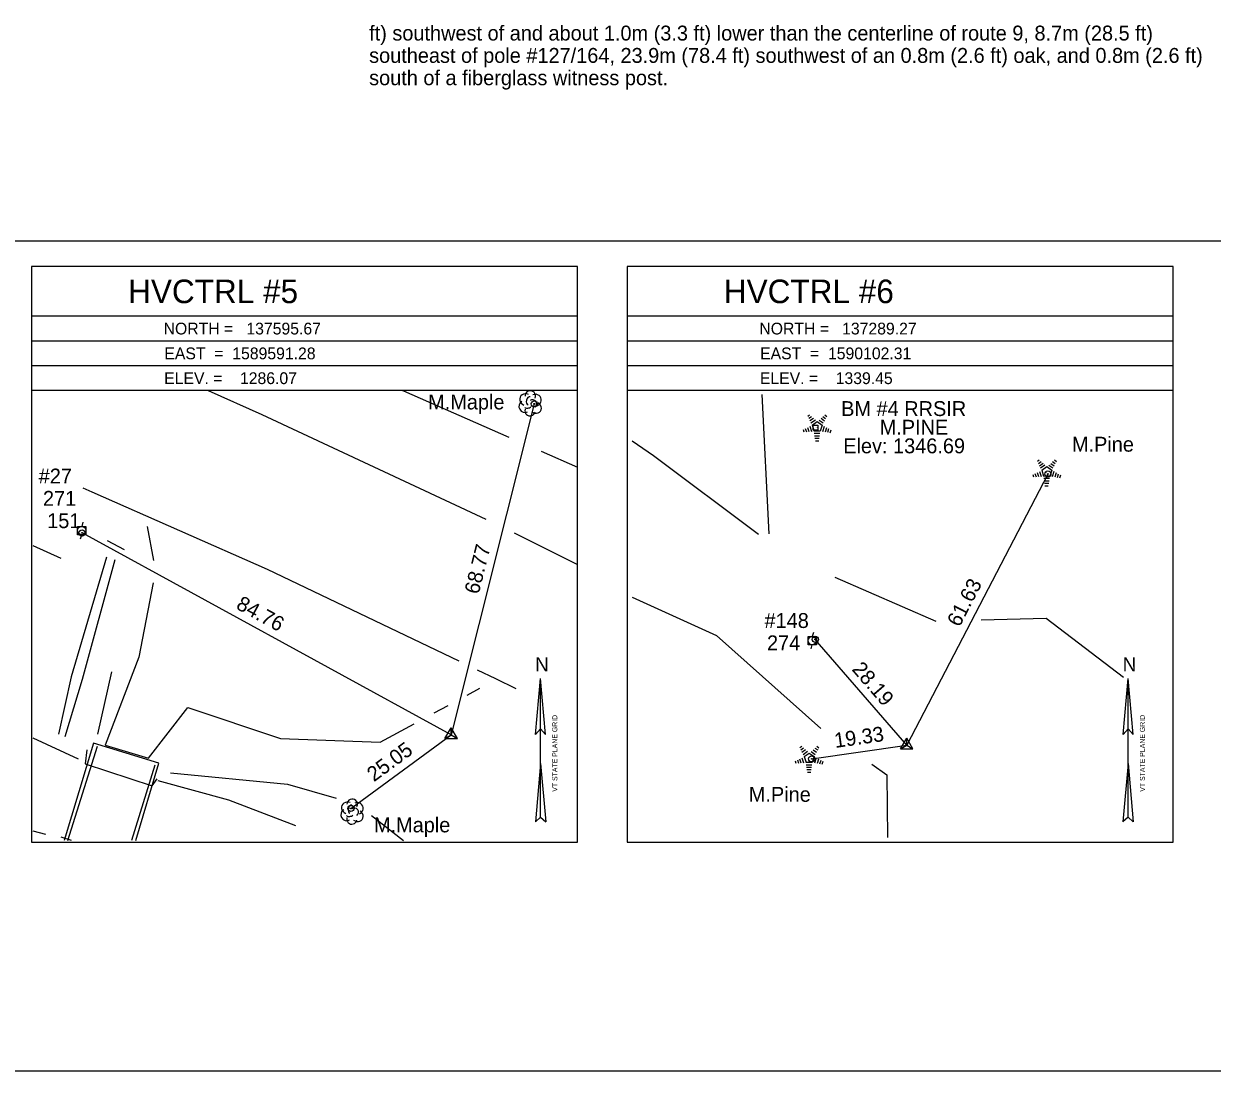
# Model space of a CAD drawing. Extents: x 1589528 to 1590208, y 135765 to 136632.
# Drawn here: x 1589811.7 to 1590051.1, y 136211.9 to 136423 of the extents above; entities that cross this region are included whole.
import ezdxf

# ---------------------------------------------------------------- set-up
doc = ezdxf.new("R2010")
doc.units = 0
for name, color, linetype in [('BELB', 7, 'Continuous'), ('BR', 7, 'Continuous'), ('BSUBM', 7, 'Continuous'), ('C_C', 7, 'Continuous'), ('CBP', 7, 'Continuous'), ('CPBM', 7, 'Continuous'), ('CPSM', 7, 'Continuous'), ('DD', 7, 'Continuous'), ('Default', 7, 'Continuous'), ('DHW', 7, 'Continuous'), ('L_C', 7, 'Continuous'), ('LAWA', 7, 'Continuous'), ('LAWE', 7, 'Continuous'), ('Level 1', 7, 'Continuous'), ('Level 2', 7, 'Continuous'), ('LTC', 7, 'Continuous'), ('LTD', 7, 'Continuous'), ('LWS', 7, 'Continuous'), ('NBL1', 7, 'Continuous'), ('PET', 7, 'Continuous'), ('RDG', 7, 'Continuous'), ('U_C', 7, 'Continuous'), ('UP', 7, 'Continuous')]:
    doc.layers.add(name, color=color, linetype=linetype)

msp = doc.modelspace()

# ---------------------------------------------------------------- linework, layer by layer
at = {"layer": 'BELB'}
for points in [[(1589838.91, 136274), (1589825.7, 136278.05), (1589819.83, 136258.41)], [(1589834.24, 136258.41), (1589838.91, 136274)]]:
    msp.add_lwpolyline(points, dxfattribs=at)
at = {"layer": 'BR'}
for points in [[(1589820.54, 136258.41), (1589826.49, 136277.43)], [(1589838.1, 136273.58), (1589833.39, 136258.41)]]:
    msp.add_lwpolyline(points, dxfattribs=at)
at = {"layer": 'BSUBM'}
for points in [[(1589824.37, 136276.67), (1589824.06, 136273.89), (1589837.54, 136269.46), (1589838.52, 136270.86)], [(1589821.28, 136258.41), (1589819.23, 136259.07)]]:
    msp.add_lwpolyline(points, dxfattribs=at)
at = {"layer": 'CBP'}
for centre, radius in [((1589914.5, 136346.42), 0.625), ((1589914.5, 136346.42), 0.0833), ((1590017.96, 136332.29), 0.625), ((1590017.96, 136332.29), 0.0833), ((1589823.41, 136320.42), 0.625), ((1589823.41, 136320.42), 0.0833), ((1589971.11, 136298.95), 0.625), ((1589971.11, 136298.95), 0.0833), ((1589970.4, 136274.88), 0.625), ((1589970.4, 136274.88), 0.0833), ((1589877.57, 136264.89), 0.625), ((1589877.57, 136264.89), 0.0833)]:
    msp.add_circle(centre, radius, dxfattribs=at)
at = {"layer": 'CPBM'}
for p, q in [((1589970.65, 136341.14), (1589970.65, 136342.14)), ((1589970.65, 136342.14), (1589971.65, 136342.14)), ((1589971.65, 136342.14), (1589971.65, 136341.14)), ((1589971.65, 136341.14), (1589970.65, 136341.14)), ((1589971.16, 136341.64), (1589971.16, 136341.64)), ((1589971.16, 136341.64), (1589971.16, 136341.64))]:
    msp.add_line(p, q, dxfattribs=at)
at = {"layer": 'CPSM'}
for p, q in [((1589896.51, 136278.99), (1589897.76, 136281.16)), ((1589896.51, 136278.99), (1589897.76, 136279.71)), ((1589899.01, 136278.99), (1589897.76, 136281.16)), ((1589897.76, 136279.71), (1589897.76, 136281.16)), ((1589897.76, 136279.71), (1589897.76, 136279.71)), ((1589897.76, 136279.71), (1589899.01, 136278.99)), ((1589896.51, 136278.99), (1589899.01, 136278.99)), ((1589988.28, 136276.89), (1589989.53, 136279.05)), ((1589988.28, 136276.89), (1589989.53, 136277.61)), ((1589990.78, 136276.89), (1589989.53, 136279.05)), ((1589989.53, 136277.61), (1589989.53, 136279.05)), ((1589989.53, 136277.61), (1589989.53, 136277.61)), ((1589989.53, 136277.61), (1589990.78, 136276.89)), ((1589988.28, 136276.89), (1589990.78, 136276.89))]:
    msp.add_line(p, q, dxfattribs=at)
at = {"layer": 'DD'}
for points in [[(1589828.32, 136315.54), (1589821.25, 136291.38), (1589818.67, 136279.89)], [(1589820.02, 136279.37), (1589823.47, 136290.94), (1589830.08, 136315.06)]]:
    msp.add_lwpolyline(points, dxfattribs=at)
at = {"layer": 'Default'}
for p, q in [((1589914.5, 136346.42), (1589897.76, 136279.71)), ((1590017.96, 136332.29), (1589989.53, 136277.61)), ((1589897.76, 136279.71), (1589823.41, 136320.42)), ((1589989.53, 136277.61), (1589971.11, 136298.95)), ((1589877.57, 136264.89), (1589897.76, 136279.71)), ((1589970.4, 136274.88), (1589989.53, 136277.61))]:
    msp.add_line(p, q, dxfattribs=at)
at = {"layer": 'DHW'}
msp.add_lwpolyline([(1589828.47, 136318.9), (1589831.91, 136317.09)], dxfattribs=at)
at = {"layer": 'LAWA'}
for points in [[(1589887.97, 136349.09), (1589888.13, 136349.03), (1589909.36, 136339.74)], [(1589934.22, 136338.96), (1589938.55, 136336.02), (1589959.69, 136320.14)], [(1589915.87, 136336.88), (1589923.23, 136333.66)], [(1589813.5, 136317.87), (1589819.14, 136315.35)], [(1589975.07, 136311.5), (1589995.39, 136302.66)], [(1589934.22, 136307.46), (1589951.2, 136299.75), (1589972.2, 136281.01)], [(1590004.54, 136302.89), (1590017.64, 136303.23), (1590033.19, 136291.36)], [(1589829.36, 136292.45), (1589826.52, 136279.85)], [(1589982.53, 136273.8), (1589985.54, 136271.69), (1589985.65, 136259.01)], [(1589841.21, 136272.07), (1589864.81, 136269.78), (1589874.61, 136266.96)], [(1589881.71, 136263.45), (1589888.16, 136258.41)]]:
    msp.add_lwpolyline(points, dxfattribs=at)
at = {"layer": 'LAWE'}
for points in [[(1589813.5, 136279.12), (1589822.64, 136274.92)], [(1589838.69, 136270.52), (1589852.9, 136266.63), (1589866.43, 136261.43)], [(1589813.5, 136260.36), (1589816.06, 136259.72)]]:
    msp.add_lwpolyline(points, dxfattribs=at)
at = {"layer": 'Level 1'}
for p, q in [((1589914.76, 136279.82), (1589915.76, 136291.05)), ((1589915.76, 136263.12), (1589915.76, 136291.05)), ((1589916.76, 136279.82), (1589915.76, 136291.05)), ((1590033.12, 136279.82), (1590034.12, 136291.05)), ((1590034.12, 136263.12), (1590034.12, 136291.05)), ((1590035.12, 136279.82), (1590034.12, 136291.05)), ((1589914.76, 136279.82), (1589915.76, 136280.92)), ((1589916.76, 136279.82), (1589915.76, 136280.92)), ((1590033.12, 136279.82), (1590034.12, 136280.92)), ((1590035.12, 136279.82), (1590034.12, 136280.92)), ((1589915.77, 136273.97), (1589914.73, 136262.2)), ((1589915.76, 136273.97), (1589916.81, 136262.2)), ((1590034.13, 136273.97), (1590033.08, 136262.2)), ((1590034.12, 136273.97), (1590035.16, 136262.2)), ((1589915.76, 136263.12), (1589914.73, 136262.2)), ((1589915.76, 136263.12), (1589916.81, 136262.2)), ((1590034.12, 136263.12), (1590033.08, 136262.2)), ((1590034.12, 136263.12), (1590035.16, 136262.2))]:
    msp.add_line(p, q, dxfattribs=at)
at = {"layer": 'LTC'}
for p, q in [((1589969.62, 136343.97), (1589969.97, 136344.23)), ((1589969.83, 136343.51), (1589970.35, 136343.89)), ((1589970.04, 136343.04), (1589970.74, 136343.55)), ((1589970.24, 136342.58), (1589971.12, 136343.21)), ((1589970.47, 136342.12), (1589971.48, 136342.86)), ((1589970.47, 136342.12), (1589970.86, 136340.93)), ((1589971.48, 136342.86), (1589972.48, 136342.13)), ((1589971.9, 136343.17), (1589972.71, 136342.58)), ((1589972.48, 136342.13), (1589972.09, 136340.93)), ((1589972.27, 136343.52), (1589972.95, 136343.02)), ((1589972.64, 136343.87), (1589973.19, 136343.47)), ((1589973.01, 136344.21), (1589973.43, 136343.91)), ((1589968.65, 136341.25), (1589968.8, 136340.78)), ((1589969.1, 136341.47), (1589969.32, 136340.82)), ((1589969.56, 136341.69), (1589969.83, 136340.85)), ((1589970.01, 136341.9), (1589970.35, 136340.88)), ((1589972.09, 136340.93), (1589970.86, 136340.93)), ((1589972.05, 136340.43), (1589970.9, 136340.43)), ((1589971.96, 136339.93), (1589970.98, 136339.93)), ((1589972.92, 136341.86), (1589972.58, 136340.82)), ((1589973.36, 136341.61), (1589973.07, 136340.72)), ((1589973.8, 136341.36), (1589973.57, 136340.63)), ((1589974.25, 136341.11), (1589974.06, 136340.53)), ((1589971.88, 136339.43), (1589971.05, 136339.43)), ((1589971.8, 136338.93), (1589971.12, 136338.93)), ((1590015.87, 136334.9), (1590016.22, 136335.15)), ((1590016.08, 136334.43), (1590016.61, 136334.81)), ((1590018.9, 136334.79), (1590019.45, 136334.39)), ((1590019.27, 136335.14), (1590019.69, 136334.83)), ((1590015.36, 136332.39), (1590015.57, 136331.74)), ((1590015.81, 136332.61), (1590016.08, 136331.77)), ((1590016.27, 136332.82), (1590016.6, 136331.8)), ((1590016.29, 136333.96), (1590016.99, 136334.48)), ((1590016.5, 136333.5), (1590017.38, 136334.14)), ((1590016.72, 136333.04), (1590017.73, 136333.78)), ((1590016.72, 136333.04), (1590017.11, 136331.85)), ((1590017.73, 136333.78), (1590018.73, 136333.05)), ((1590018.15, 136334.09), (1590018.96, 136333.5)), ((1590018.73, 136333.05), (1590018.34, 136331.85)), ((1590018.53, 136334.44), (1590019.2, 136333.95)), ((1590019.17, 136332.78), (1590018.83, 136331.74)), ((1590019.61, 136332.53), (1590019.33, 136331.65)), ((1590014.9, 136332.17), (1590015.05, 136331.71)), ((1590018.34, 136331.85), (1590017.11, 136331.85)), ((1590018.3, 136331.35), (1590017.16, 136331.35)), ((1590018.22, 136330.85), (1590017.23, 136330.85)), ((1590018.13, 136330.35), (1590017.3, 136330.35)), ((1590020.06, 136332.28), (1590019.82, 136331.55)), ((1590020.5, 136332.03), (1590020.32, 136331.46)), ((1590018.05, 136329.85), (1590017.38, 136329.85)), ((1589968.01, 136277.18), (1589968.37, 136277.44)), ((1589971.41, 136277.42), (1589971.83, 136277.12)), ((1589968.22, 136276.72), (1589968.75, 136277.1)), ((1589968.41, 136275.11), (1589968.74, 136274.09)), ((1589968.43, 136276.25), (1589969.13, 136276.76)), ((1589968.64, 136275.78), (1589969.52, 136276.42)), ((1589968.86, 136275.33), (1589969.88, 136276.06)), ((1589968.86, 136275.33), (1589969.25, 136274.14)), ((1589969.88, 136276.06), (1589970.87, 136275.34)), ((1589970.3, 136276.38), (1589971.11, 136275.79)), ((1589970.87, 136275.34), (1589970.48, 136274.14)), ((1589970.67, 136276.72), (1589971.35, 136276.23)), ((1589971.31, 136275.07), (1589970.97, 136274.03)), ((1589971.04, 136277.07), (1589971.59, 136276.67)), ((1589967.04, 136274.46), (1589967.2, 136273.99)), ((1589967.5, 136274.68), (1589967.71, 136274.03)), ((1589967.95, 136274.89), (1589968.23, 136274.06)), ((1589970.48, 136274.14), (1589969.25, 136274.14)), ((1589970.44, 136273.64), (1589969.3, 136273.64)), ((1589970.36, 136273.14), (1589969.37, 136273.14)), ((1589970.28, 136272.64), (1589969.44, 136272.64)), ((1589971.76, 136274.82), (1589971.47, 136273.93)), ((1589972.2, 136274.57), (1589971.96, 136273.84)), ((1589972.64, 136274.32), (1589972.46, 136273.74)), ((1589970.19, 136272.14), (1589969.52, 136272.14))]:
    msp.add_line(p, q, dxfattribs=at)
at = {"layer": 'LTD'}
for p, q in [((1589913.66, 136346.59), (1589913.66, 136346.59)), ((1589913.66, 136346.59), (1589913.66, 136346.59)), ((1589877.77, 136264.3), (1589877.77, 136264.3)), ((1589877.77, 136264.3), (1589877.77, 136264.3))]:
    msp.add_line(p, q, dxfattribs=at)
for centre in [(1589913.7, 136348.02), (1589877.82, 136265.74)]:
    msp.add_arc(centre, 1.05, 335.5272, 180.9563, dxfattribs=at)
for centre, major_axis, ratio, start_param, end_param in [((1589912.57, 136345.88), (0.58, -1.04), 0.959034, 3.141593, 6.283185), ((1589912.87, 136347.25), (1.21, -0.51), 0.895232, 1.570796, 4.712389), ((1589913.45, 136347.05), (-0.208, -0.792), 0.645439, 3.141593, 6.283185), ((1589914.16, 136346.42), (-0.5, 0.667), 0.989748, 3.141593, 6.283185), ((1589914.7, 136347.17), (-1.14, -0.48), 0.949671, 1.570796, 4.712389), ((1589913.66, 136345.09), (0.26, 1.06), 0.942809, 1.570796, 4.712389), ((1589913.2, 136345.84), (-0.625, -0.083), 0.423636, 0, 3.141593), ((1589914.66, 136345.76), (-1.09, 0.79), 0.841452, 1.570796, 4.712389), ((1589876.98, 136264.97), (1.21, -0.51), 0.895232, 1.570796, 4.712389), ((1589877.56, 136264.76), (-0.208, -0.792), 0.645439, 3.141593, 6.283185), ((1589878.81, 136264.89), (-1.14, -0.48), 0.949671, 1.570796, 4.712389), ((1589876.69, 136263.6), (0.58, -1.04), 0.959034, 3.141593, 6.283185), ((1589877.77, 136262.8), (0.26, 1.06), 0.942809, 1.570796, 4.712389), ((1589877.32, 136263.55), (-0.625, -0.083), 0.423636, 0, 3.141593), ((1589878.27, 136264.14), (-0.5, 0.667), 0.989748, 3.141593, 6.283185), ((1589878.77, 136263.47), (-1.09, 0.79), 0.841452, 1.570796, 4.712389)]:
    msp.add_ellipse(centre, major_axis=major_axis, ratio=ratio, start_param=start_param, end_param=end_param, dxfattribs=at)
at = {"layer": 'LWS'}
msp.add_lwpolyline([(1589961.84, 136320.21), (1589960.42, 136348.33)], dxfattribs=at)
at = {"layer": 'NBL1'}
for p, q in [((1589528.23, 136379.26), (1590208.23, 136379.26)), ((1589923.23, 136364.09), (1589813.23, 136364.09)), ((1590043.23, 136364.09), (1589933.23, 136364.09)), ((1589923.23, 136359.09), (1589813.23, 136359.09)), ((1590043.23, 136359.09), (1589933.23, 136359.09)), ((1589923.23, 136354.09), (1589813.23, 136354.09)), ((1590043.23, 136354.09), (1589933.23, 136354.09)), ((1589923.23, 136349.09), (1589813.23, 136349.09)), ((1590043.23, 136349.09), (1589933.23, 136349.09))]:
    msp.add_line(p, q, dxfattribs=at)
for points in [[(1590208.23, 136211.93), (1589528.23, 136211.93), (1589528.23, 136631.93), (1590208.23, 136631.93)], [(1589813.23, 136258.09), (1589923.23, 136258.09), (1589923.23, 136374.09), (1589813.23, 136374.09)], [(1589933.23, 136258.09), (1590043.23, 136258.09), (1590043.23, 136374.09), (1589933.23, 136374.09)]]:
    msp.add_lwpolyline(points, close=True, dxfattribs=at)
at = {"layer": 'PET'}
for points in [[(1589848.81, 136349.09), (1589859.62, 136344.3), (1589904.77, 136323.16)], [(1589899.35, 136294.57), (1589860.74, 136313.03), (1589825.44, 136328.63), (1589823.62, 136329.42)], [(1589910.43, 136320.44), (1589923.23, 136314.04)], [(1589910.86, 136288.97), (1589906.74, 136291.04), (1589903.09, 136292.78)]]:
    msp.add_lwpolyline(points, dxfattribs=at)
at = {"layer": 'RDG'}
for points in [[(1589836.52, 136321.72), (1589837.83, 136314.84)], [(1589837.71, 136310.36), (1589834.88, 136295.37), (1589828.07, 136277.63), (1589836.78, 136274.99), (1589844.7, 136285.23), (1589863.37, 136279), (1589883.45, 136278.22), (1589890.29, 136281.93)], [(1589900.96, 136287.73), (1589903.53, 136289.12)], [(1589894.33, 136284.13), (1589897.13, 136285.65)]]:
    msp.add_lwpolyline(points, dxfattribs=at)
at = {"layer": 'UP'}
for p, q in [((1589822.51, 136320.06), (1589822.51, 136321.73)), ((1589822.51, 136321.73), (1589824.17, 136321.73)), ((1589823.59, 136322.56), (1589823.34, 136321.73)), ((1589823.34, 136320.89), (1589823.34, 136320.89)), ((1589824.17, 136321.73), (1589824.17, 136320.06)), ((1589824.17, 136320.06), (1589822.51, 136320.06)), ((1589823.09, 136319.23), (1589823.34, 136320.06)), ((1589969.66, 136297.87), (1589969.66, 136299.54)), ((1589969.66, 136299.54), (1589971.33, 136299.54)), ((1589970.75, 136300.37), (1589970.5, 136299.54)), ((1589971.33, 136299.54), (1589971.33, 136297.87)), ((1589971.33, 136297.87), (1589969.66, 136297.87)), ((1589970.25, 136297.04), (1589970.5, 136297.87)), ((1589970.5, 136298.71), (1589970.5, 136298.71))]:
    msp.add_line(p, q, dxfattribs=at)
for centre in [(1589823.34, 136320.89), (1589970.5, 136298.71)]:
    msp.add_circle(centre, 0.833, dxfattribs=at)

# ---------------------------------------------------------------- texts
at = {"layer": 'C_C'}
for s, p in [('BM #4 RRSIR', (1589976.32, 136343.97)), ('M.PINE', (1589984.08, 136340.21)), ('Elev: 1346.69', (1589976.74, 136336.46))]:
    msp.add_text(s, height=3, dxfattribs=at).set_placement(p)
at = {"layer": 'Default'}
for p in [(1589893.12, 136345.3), (1589882.21, 136260.07)]:
    msp.add_text('M.Maple', height=3, dxfattribs=at).set_placement(p)
for s, rotation, p in [('68.77', 75.9079, (1589903.29, 136307.92)), ('61.63', 62.5276, (1590000.15, 136301.29)), ('84.76', 331.3007, (1589854.24, 136305.25)), ('28.19', 310.8104, (1589978.34, 136292.86)), ('19.33', 8.112, (1589975.15, 136277.08)), ('25.05', 36.2932, (1589882.2, 136270.15))]:
    msp.add_text(s, height=3, rotation=rotation, dxfattribs=at).set_placement(p)
at = {"layer": 'L_C'}
for p in [(1590022.81, 136336.79), (1589957.72, 136266.23)]:
    msp.add_text('M.Pine', height=3, dxfattribs=at).set_placement(p)
at = {"layer": 'Level 1'}
for p in [(1589914.66, 136292.51), (1590033.02, 136292.51)]:
    msp.add_text('N', height=2.85, dxfattribs=at).set_placement(p)
for p in [(1589919.15, 136268.26), (1590037.51, 136268.26)]:
    msp.add_text('VT STATE PLANE GRID', height=1.0092, rotation=90.0204, dxfattribs=at).set_placement(p)
at = {"layer": 'Level 2'}
for s, p in [('ft) southwest of and about 1.0m (3.3 ft) lower than the centerline of route 9, 8.7m (28.5 ft) ', (1589881.24, 136419.65)), ('southeast of pole #127/164, 23.9m (78.4 ft) southwest of an 0.8m (2.6 ft) oak, and 0.8m (2.6 ft) ', (1589881.24, 136415.15)), ('south of a fiberglass witness post.', (1589881.24, 136410.65))]:
    msp.add_text(s, height=3, dxfattribs=at).set_placement(p)
at = {"layer": 'LTC'}
for p in [(1589971.36, 136341.87), (1590017.62, 136332.79), (1589969.76, 136275.08)]:
    msp.add_text('.', height=1.04, rotation=270, dxfattribs=at).set_placement(p)
at = {"layer": 'NBL1'}
for s, height, p in [('     HVCTRL #5     ', 4.75, (1589823.87, 136366.72)), ('     HVCTRL #6     ', 4.75, (1589943.87, 136366.72)), ('NORTH =   137595.67 ', 2.375, (1589839.84, 136360.41)), ('NORTH =   137289.27 ', 2.375, (1589959.84, 136360.41)), ('EAST  =  1589591.28 ', 2.375, (1589839.99, 136355.41)), ('EAST  =  1590102.31 ', 2.375, (1589959.99, 136355.41)), ('ELEV. =    1286.07  ', 2.375, (1589839.95, 136350.41)), ('ELEV. =    1339.45  ', 2.375, (1589959.95, 136350.41))]:
    msp.add_text(s, height=height, dxfattribs=at).set_placement(p)
at = {"layer": 'U_C'}
for s, p in [('#27', (1589814.68, 136330.38)), ('271', (1589815.54, 136325.88)), ('151', (1589816.39, 136321.38)), ('#148', (1589960.88, 136301.26)), ('274', (1589961.38, 136296.76))]:
    msp.add_text(s, height=3, dxfattribs=at).set_placement(p)

doc.saveas('drawing.dxf')
